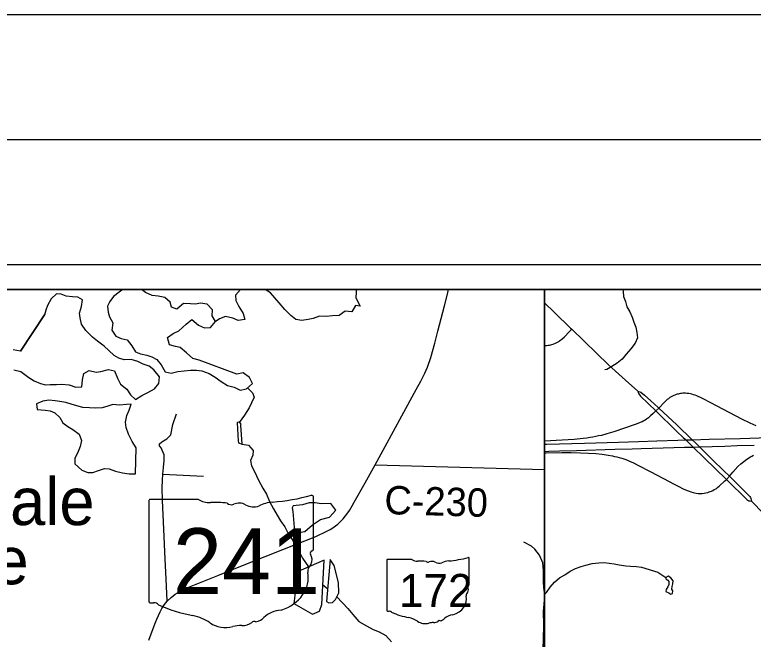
# Model space of a CAD drawing. Extents: x 25.6 to 80.6, y 0.2 to 24.5.
# Drawn here: x 38.894 to 41.848, y 19.73 to 22.23 of the extents above; entities that cross this region are included whole.
import ezdxf

# ---------------------------------------------------------------- set-up
doc = ezdxf.new("R2010")
doc.units = 0
for name, color, linetype in [('GM_X_County_Road', 7, 'Continuous'), ('GM_X_County_Road_Text', 7, 'Continuous'), ('GM_X_Interchange_Ramps', 7, 'Continuous'), ('GM_X_Interstate_Route', 7, 'Continuous'), ('GM_X_Minor_Lake', 7, 'Continuous'), ('GM_X_Minor_Lake_Text', 7, 'Continuous'), ('GM_X_Minor_River', 7, 'Continuous'), ('GM_X_State_Location', 7, 'Continuous'), ('GM_X_State_Route', 7, 'Continuous'), ('GM_X_State_Shield', 7, 'Continuous'), ('GM_X_Township_Road', 7, 'Continuous'), ('SH_Border', 7, 'Continuous'), ('SH_Cut_Line', 7, 'Continuous'), ('SH_Data', 7, 'Continuous'), ('SH_Text', 7, 'Continuous')]:
    doc.layers.add(name, color=color, linetype=linetype)

msp = doc.modelspace()

# ---------------------------------------------------------------- linework, layer by layer
at = {"layer": 'GM_X_County_Road'}
msp.add_line((40.3351, 20.429), (41.0128, 20.4098), dxfattribs=at)
at = {"layer": 'GM_X_Interchange_Ramps'}
for points in [[(41.8598, 20.5842), (41.8474, 20.5895), (41.8348, 20.5953), (41.8015, 20.612), (41.6785, 20.6768), (41.6477, 20.6929), (41.637, 20.698), (41.6272, 20.7027), (41.6218, 20.705), (41.6157, 20.7072), (41.6087, 20.7095), (41.6026, 20.7113), (41.5966, 20.7128), (41.5903, 20.7139), (41.5832, 20.7147), (41.5765, 20.7151), (41.571, 20.7151), (41.5664, 20.715), (41.5614, 20.7145), (41.557, 20.7139), (41.5518, 20.713), (41.5472, 20.712), (41.5431, 20.7109), (41.5389, 20.7096), (41.534, 20.708), (41.5296, 20.7061), (41.525, 20.7039), (41.52, 20.7011), (41.5142, 20.6977), (41.5083, 20.6934), (41.5035, 20.6895), (41.4979, 20.6846), (41.4925, 20.6794), (41.47, 20.656), (41.4587, 20.6442)], [(41.4587, 20.6442), (41.4473, 20.6337), (41.4372, 20.6245), (41.4288, 20.6171), (41.421, 20.611), (41.4158, 20.6076), (41.4104, 20.6045), (41.4031, 20.6007), (41.3959, 20.5975), (41.386, 20.5936), (41.375, 20.5896), (41.2902, 20.5612), (41.2617, 20.5525), (41.2401, 20.5467), (41.2291, 20.5441), (41.2183, 20.5417), (41.2067, 20.5395), (41.1951, 20.5375), (41.1825, 20.5357), (41.168, 20.5338), (41.1309, 20.5304), (41.0838, 20.5272), (41.0128, 20.5234)], [(41.0128, 20.4765), (41.0196, 20.4765), (41.0814, 20.4777), (41.1199, 20.4779), (41.1572, 20.4771), (41.1883, 20.4756), (41.218, 20.4734), (41.2428, 20.4709), (41.2674, 20.4676), (41.2845, 20.4644), (41.2933, 20.4626), (41.302, 20.4607), (41.312, 20.458), (41.3219, 20.455), (41.3335, 20.4511), (41.3441, 20.447), (41.3557, 20.4422), (41.3658, 20.4377), (41.3893, 20.4264), (41.4354, 20.4018), (41.4881, 20.3738), (41.5311, 20.3514), (41.5477, 20.3429), (41.5679, 20.3331), (41.5838, 20.3259), (41.591, 20.323), (41.5978, 20.3207), (41.6073, 20.3179), (41.6134, 20.3164), (41.6201, 20.3151), (41.6272, 20.3144), (41.6354, 20.3141), (41.6436, 20.3144), (41.651, 20.3152), (41.6586, 20.3166), (41.6662, 20.3185), (41.671, 20.3199), (41.6756, 20.3217), (41.6807, 20.3237), (41.6859, 20.3262), (41.6919, 20.3295), (41.6975, 20.333), (41.7016, 20.3357), (41.7066, 20.3394), (41.7116, 20.3435), (41.7345, 20.3647), (41.7406, 20.3703)], [(41.7406, 20.3703), (41.7524, 20.3838), (41.7662, 20.3997), (41.7864, 20.4214), (41.7982, 20.4324), (41.8097, 20.4419), (41.8227, 20.4514), (41.8364, 20.4601), (41.8425, 20.4636), (41.8494, 20.4673)]]:
    msp.add_lwpolyline(points, dxfattribs=at)
at = {"layer": 'GM_X_Interstate_Route'}
for points in [[(41.0128, 20.5109), (41.0222, 20.5112), (41.1725, 20.5159), (41.3093, 20.5196), (41.3888, 20.5224), (41.4619, 20.5246), (41.5466, 20.5275), (41.5778, 20.5283), (41.604, 20.529), (41.6721, 20.5308), (41.7951, 20.5346), (41.9095, 20.5377)], [(41.5733, 20.4988), (41.5875, 20.4992), (41.607, 20.4998), (41.6331, 20.5007), (41.7341, 20.5039), (41.7838, 20.5054), (41.8509, 20.5074)], [(41.0128, 20.4823), (41.0295, 20.4828), (41.073, 20.4843), (41.1413, 20.4864), (41.2942, 20.4911), (41.3638, 20.493), (41.3998, 20.4939), (41.488, 20.4963), (41.5733, 20.4988)]]:
    msp.add_lwpolyline(points, dxfattribs=at)
at = {"layer": 'GM_X_Minor_Lake'}
msp.add_line((41.5096, 19.9622), (41.5105, 19.95), dxfattribs=at)
for points in [[(39.3265, 21.1303), (39.3118, 21.1196), (39.2885, 21.1019), (39.2743, 21.0827), (39.2639, 21.0636), (39.2673, 21.0401), (39.2728, 21.0205), (39.286, 20.9971), (39.2825, 20.9682), (39.2973, 20.9433), (39.3186, 20.9337), (39.3429, 20.9286), (39.3614, 20.9053), (39.3769, 20.8812), (39.3967, 20.8731), (39.4225, 20.8673), (39.4416, 20.8607), (39.4614, 20.8503), (39.4791, 20.8285), (39.4954, 20.8006), (39.5189, 20.7955), (39.5462, 20.8027), (39.5712, 20.8045), (39.5962, 20.807), (39.6212, 20.8073), (39.6424, 20.8053), (39.6706, 20.7942), (39.6951, 20.7801), (39.7195, 20.7622), (39.7448, 20.7465), (39.7706, 20.74), (39.795, 20.7274), (39.8208, 20.733), (39.844, 20.7545), (39.8323, 20.7779), (39.8078, 20.7966), (39.7814, 20.791)], [(39.6313, 20.8477), (39.6062, 20.8542), (39.5809, 20.8767), (39.5556, 20.8985), (39.5366, 20.902), (39.5123, 20.9093), (39.5051, 20.9389), (39.5269, 20.9543), (39.5503, 20.9652), (39.5788, 20.9914), (39.602, 21.0106), (39.6281, 20.9874), (39.6532, 20.977), (39.676, 20.9788), (39.6969, 21.0026), (39.6838, 21.0252), (39.685, 21.0488), (39.6635, 21.0713), (39.6369, 21.0756), (39.6172, 21.0723), (39.596, 21.0736), (39.5686, 21.0748), (39.5416, 21.0524), (39.5203, 21.0598), (39.5155, 21.0802), (39.494, 21.099), (39.4667, 21.1032), (39.4431, 21.106), (39.4172, 21.1186), (39.4003, 21.1303)], [(38.8894, 20.8087), (38.9175, 20.8022), (38.9497, 20.7783), (38.9711, 20.7648), (38.997, 20.7538), (39.0167, 20.7494), (39.0357, 20.7504), (39.06, 20.7507), (39.0804, 20.7517), (39.1108, 20.749), (39.1374, 20.7394), (39.1624, 20.7413), (39.1651, 20.7686), (39.1701, 20.7945), (39.1912, 20.8061), (39.2186, 20.7989), (39.2383, 20.8021), (39.2685, 20.8101), (39.2921, 20.8043), (39.3046, 20.7756), (39.317, 20.7514), (39.3423, 20.732), (39.3562, 20.7086), (39.3769, 20.6906), (39.4025, 20.7061), (39.4259, 20.7185), (39.453, 20.7325), (39.4702, 20.7539), (39.4721, 20.7813), (39.4505, 20.8091), (39.4306, 20.8233), (39.407, 20.8314), (39.3857, 20.8426), (39.3598, 20.8499), (39.3317, 20.8495), (39.3104, 20.8554), (39.2906, 20.8658), (39.2699, 20.8868), (39.2507, 20.904), (39.2239, 20.9235), (39.2048, 20.9392), (39.1779, 20.967), (39.1602, 20.9918), (39.1546, 21.0168), (39.1528, 21.0358), (39.1601, 21.0624), (39.1643, 21.0891), (39.1452, 21.1002), (39.1247, 21.1015), (39.0989, 21.1042), (39.0798, 21.1116), (39.0601, 21.1137), (39.0391, 21.0929), (39.025, 21.0669), (39.0184, 21.0479), (39.0125, 21.0294)], [(38.8894, 20.8087), (38.9175, 20.8022), (38.9497, 20.7783), (38.9711, 20.7648), (38.997, 20.7538), (39.0167, 20.7494), (39.0357, 20.7504), (39.06, 20.7507), (39.0804, 20.7517), (39.1108, 20.749), (39.1374, 20.7394), (39.1624, 20.7413), (39.1651, 20.7686), (39.1701, 20.7945), (39.1912, 20.8061), (39.2186, 20.7989), (39.2383, 20.8021), (39.2685, 20.8101), (39.2921, 20.8043), (39.3046, 20.7756), (39.317, 20.7514), (39.3423, 20.732), (39.3562, 20.7086), (39.3769, 20.6906), (39.4025, 20.7061), (39.4259, 20.7185), (39.453, 20.7325), (39.4702, 20.7539), (39.4721, 20.7813), (39.4505, 20.8091), (39.4306, 20.8233), (39.407, 20.8314), (39.3857, 20.8426), (39.3598, 20.8499), (39.3317, 20.8495), (39.3104, 20.8554), (39.2906, 20.8658), (39.2699, 20.8868), (39.2507, 20.904), (39.2239, 20.9235), (39.2048, 20.9392), (39.1779, 20.967), (39.1602, 20.9918), (39.1546, 21.0168), (39.1528, 21.0358), (39.1601, 21.0624), (39.1643, 21.0891), (39.1452, 21.1002), (39.1247, 21.1015), (39.0989, 21.1042), (39.0798, 21.1116), (39.0601, 21.1137), (39.0391, 21.0929), (39.025, 21.0669), (39.0184, 21.0479), (39.0119, 21.0273)], [(39.0125, 21.0294), (38.9165, 20.8834)], [(38.9165, 20.8834), (39.0125, 21.0293)], [(38.9165, 20.8834), (38.8877, 20.8884)], [(38.9165, 20.8834), (38.8877, 20.8884)], [(39.7814, 20.791), (39.6313, 20.8477)], [(39.3792, 20.497), (39.363, 20.5226), (39.3483, 20.5513), (39.3396, 20.5778), (39.3371, 20.599), (39.342, 20.6264), (39.3516, 20.647), (39.3589, 20.6714), (39.34, 20.6704), (39.3127, 20.6671), (39.2854, 20.6698), (39.2658, 20.6635), (39.2431, 20.6571), (39.2158, 20.6561), (39.193, 20.6566), (39.1665, 20.6585), (39.1414, 20.6643), (39.1193, 20.6717), (39.098, 20.6775), (39.0744, 20.6818), (39.0547, 20.6853), (39.0304, 20.6881), (39.0054, 20.6832), (38.9805, 20.6731), (38.9838, 20.6503), (39.0157, 20.6477), (39.0347, 20.6448), (39.0545, 20.6367), (39.0737, 20.618), (39.0853, 20.5961), (39.1052, 20.5826), (39.1258, 20.57), (39.1511, 20.5513), (39.1605, 20.5263), (39.1547, 20.502), (39.1444, 20.4753), (39.1341, 20.4554), (39.1343, 20.4326), (39.1612, 20.4071), (39.1863, 20.3983), (39.2053, 20.3985), (39.2279, 20.4064), (39.2521, 20.4143), (39.2711, 20.413), (39.297, 20.4034), (39.3243, 20.3961), (39.3509, 20.3926), (39.3767, 20.3922)], [(39.803, 20.511), (39.7973, 20.5871), (39.7996, 20.5912), (39.7938, 20.5976), (39.7897, 20.5993), (39.7851, 20.5982), (39.7828, 20.5964), (39.7874, 20.525), (39.789, 20.5165)], [(39.789, 20.5165), (39.803, 20.511)], [(39.3767, 20.3922), (39.3792, 20.497)], [(40.011, 20.1778), (40.0141, 20.1672), (40.0218, 20.1605), (40.0309, 20.1576), (40.0536, 20.1616), (40.0844, 20.1878), (40.1168, 20.2102), (40.153, 20.219), (40.1777, 20.2473), (40.1584, 20.2745), (40.119, 20.2725), (40.0955, 20.276), (40.0712, 20.2765), (40.0448, 20.2686), (40.0069, 20.2651), (40.0032, 20.2559), (40.0057, 20.2415)], [(40.0057, 20.2415), (40.011, 20.1778)], [(40.0185, 19.9972), (40.0143, 19.906), (40.0094, 19.8741), (40.0842, 19.8309), (40.1129, 19.8426), (40.1224, 19.8701), (40.1309, 20.0471)], [(40.1309, 20.0471), (40.0185, 19.9972)], [(40.1405, 19.8817), (40.1504, 19.8765), (40.164, 19.8774), (40.1768, 19.8897), (40.1893, 19.9156), (40.1888, 19.9582), (40.1713, 20.0255), (40.1559, 20.0497)], [(40.1559, 20.0497), (40.1405, 19.8817)], [(41.5105, 19.95), (41.506, 19.9408), (41.4993, 19.9301), (41.4987, 19.9218), (41.5101, 19.9158), (41.5185, 19.9106), (41.5253, 19.9137), (41.5259, 19.9236), (41.5221, 19.9304), (41.5234, 19.9418), (41.5264, 19.9517), (41.527, 19.9646), (41.5185, 19.9767), (41.507, 19.9826), (41.498, 19.978), (41.4981, 19.9726), (41.5065, 19.9674), (41.5096, 19.9622)]]:
    msp.add_lwpolyline(points, dxfattribs=at)
at = {"layer": 'GM_X_Minor_River'}
for points in [[(39.7969, 21.1303), (39.7768, 21.1076), (39.7778, 21.0871), (39.7895, 21.0622), (39.8072, 21.0343), (39.8144, 21.0101), (39.7871, 21.0067), (39.7658, 21.0163), (39.7369, 21.0221), (39.712, 21.0127), (39.6958, 21.0014)], [(40.2589, 21.1303), (40.2597, 21.1193), (40.2585, 21.0965), (40.2755, 21.0633), (40.2565, 21.0661), (40.2417, 21.0408), (40.2159, 21.0443), (40.1918, 21.0266), (40.1645, 21.0255), (40.1388, 21.0222), (40.1122, 21.0242), (40.0873, 21.0147), (40.0669, 21.01), (40.0419, 21.0059), (40.0176, 21.0109), (39.9984, 21.0259), (39.9746, 21.0499), (39.9508, 21.0769), (39.9346, 21.0965), (39.9162, 21.1175), (39.8959, 21.1303)], [(41.3259, 21.1303), (41.3275, 21.123), (41.3285, 21.1025), (41.3363, 21.0828), (41.3419, 21.0609), (41.3543, 21.0405), (41.3629, 21.0193), (41.3707, 20.9997), (41.3777, 20.9793), (41.3825, 20.9588), (41.3843, 20.9376), (41.3755, 20.9154), (41.3576, 20.8924), (41.3389, 20.8717), (41.324, 20.851), (41.3037, 20.8355), (41.2819, 20.8216), (41.2623, 20.8107), (41.254, 20.8083)], [(39.8251, 20.737), (39.8345, 20.7276), (39.8449, 20.7172), (39.8519, 20.6992), (39.8403, 20.6771), (39.8315, 20.6562), (39.8124, 20.6278), (39.7915, 20.5986)], [(39.803, 20.511), (39.828, 20.5068), (39.8472, 20.4865), (39.846, 20.4675), (39.8364, 20.4454), (39.8412, 20.4249), (39.8521, 20.4015), (39.8692, 20.3668), (39.8855, 20.3358), (39.9009, 20.3109), (39.9127, 20.2815), (39.9282, 20.252), (39.9429, 20.2271), (39.9561, 20.2038), (39.9738, 20.1804), (39.9862, 20.1563), (40.0001, 20.1337), (40.0195, 20.105), (40.0311, 20.0816), (40.0443, 20.0552), (40.0692, 20.0197)], [(41.0128, 19.9092), (41.0208, 19.9181), (41.0349, 19.9395), (41.0521, 19.9595), (41.0731, 19.9757), (41.0942, 19.9881), (41.1159, 20.0036), (41.137, 20.0137), (41.1589, 20.0216), (41.1785, 20.0271), (41.2034, 20.0343), (41.2299, 20.0361), (41.2519, 20.0372), (41.2716, 20.0352), (41.2913, 20.0324), (41.3118, 20.0288), (41.3376, 20.0246), (41.3573, 20.0225), (41.3808, 20.0221), (41.4013, 20.0193), (41.4661, 19.9994), (41.498, 19.978)], [(40.1451, 19.9329), (40.1261, 19.9475)], [(40.182, 19.9005), (40.2257, 19.8538), (40.2465, 19.8297), (40.2703, 19.8012), (40.3001, 19.7848), (40.3276, 19.7692), (40.3512, 19.7596), (40.3779, 19.7455), (40.401, 19.7207)]]:
    msp.add_lwpolyline(points, dxfattribs=at)
at = {"layer": 'GM_X_State_Route'}
msp.add_line((41.568, 20.5379), (41.575, 20.531), dxfattribs=at)
for points in [[(39.4294, 19.7265), (39.4558, 19.7951), (39.462, 19.8113), (39.4682, 19.8261), (39.4748, 19.8397), (39.4824, 19.8538), (39.4924, 19.8691), (39.5031, 19.8823), (39.5186, 19.8979), (39.5355, 19.9104), (39.5542, 19.9214), (39.5715, 19.9303), (39.5928, 19.9398), (39.7059, 19.9861), (39.8248, 20.0331), (39.9666, 20.0896), (40.0973, 20.1423), (40.142, 20.1625), (40.1554, 20.1698), (40.1659, 20.1765), (40.1766, 20.1839), (40.1857, 20.1912), (40.1957, 20.2005), (40.2072, 20.2125), (40.217, 20.2244), (40.2256, 20.236), (40.2324, 20.2461), (40.2437, 20.2645), (40.2519, 20.2789), (40.2954, 20.357), (40.3351, 20.429), (40.3752, 20.5024), (40.4422, 20.6253), (40.4993, 20.7297), (40.5179, 20.7642), (40.5341, 20.7952), (40.5448, 20.82), (40.558, 20.8584), (40.574, 20.9151), (40.5865, 20.9639), (40.6125, 21.0646), (40.6231, 21.1067), (40.6283, 21.1303)], [(41.0128, 21.0776), (41.0527, 21.0388), (41.1167, 20.9763), (41.1214, 20.9717), (41.1696, 20.9253), (41.222, 20.874), (41.268, 20.8303), (41.2973, 20.8034), (41.3371, 20.7677), (41.386, 20.7229)], [(41.386, 20.7229), (41.3871, 20.7182), (41.3895, 20.7134), (41.3974, 20.7037), (41.4587, 20.6442), (41.5427, 20.5626), (41.568, 20.5379)], [(41.386, 20.7229), (41.3891, 20.7227), (41.3945, 20.721), (41.3977, 20.7192), (41.4127, 20.7079), (41.4381, 20.685), (41.4679, 20.658), (41.47, 20.656), (41.5422, 20.5881), (41.604, 20.529), (41.6186, 20.515), (41.6331, 20.5007), (41.684, 20.4503), (41.7303, 20.4051), (41.7524, 20.3838)], [(41.575, 20.531), (41.5778, 20.5283), (41.607, 20.4998), (41.6511, 20.4567), (41.7406, 20.3703)], [(41.7524, 20.3838), (41.7545, 20.3818), (41.7862, 20.3503), (41.8098, 20.3264), (41.8338, 20.3013), (41.8363, 20.2972), (41.8383, 20.2937), (41.84, 20.2883), (41.8408, 20.2836)], [(41.7406, 20.3703), (41.7557, 20.3556), (41.8106, 20.3016), (41.8224, 20.2896), (41.8258, 20.2868), (41.8299, 20.2849), (41.8353, 20.284), (41.8408, 20.2836)], [(41.8408, 20.2836), (41.8564, 20.2671), (41.8734, 20.2492), (41.8956, 20.2258), (41.9209, 20.2004), (41.9694, 20.1517)]]:
    msp.add_lwpolyline(points, dxfattribs=at)
at = {"layer": 'GM_X_State_Shield'}
for p, q in [((40.0884, 20.0906), (40.0884, 20.3)), ((39.4293, 20.2832), (39.4293, 19.8829)), ((39.6288, 20.2901), (39.4358, 20.2901)), ((40.0884, 20.0907), (40.0884, 20.0906)), ((40.3817, 20.046), (40.3817, 19.8458)), ((40.4814, 20.0494), (40.3849, 20.0494)), ((40.7112, 19.9497), (40.7112, 20.0544)), ((40.7112, 19.9497), (40.7112, 19.9497))]:
    msp.add_line(p, q, dxfattribs=at)
for centre, major_axis, start_param, end_param in [((39.8536, 20.8357), (0.699, 0), 4.814394, 5.042369), ((40.0811, 20.3008), (0.00734, 0), 6.141152, 7.989035), ((39.4368, 20.284), (0.00764, 0), 1.712693, 3.28349), ((39.6748, 20.3365), (0.0741, 0), 4.042523, 4.731795), ((39.6993, 20.0654), (0.2659, 0), 1.404758, 1.657858), ((39.7597, 20.2861), (0.0214, 0), 3.836095, 5.185415), ((39.7911, 20.2398), (0.0444, 0), 0.950623, 2.079405), ((39.8484, 20.3033), (0.0534, 0), 4.081561, 5.145723), ((39.9428, 20.1678), (0.1406, 0), 1.699011, 2.107814), ((40.0806, 20.0898), (0.00785, 0), 5.05454, 6.418171), ((40.0867, 20.0752), (0.0114, 0), 1.883978, 3.671073), ((40.0145, 20.0488), (0.0682, 0), 5.934695, 6.695948), ((40.1147, 20.003), (0.0496, 0), 2.387724, 3.262537), ((40.3854, 20.0464), (0.00382, 0), 1.712693, 3.28349), ((40.5044, 20.0726), (0.037, 0), 4.042523, 4.731795), ((40.5167, 19.9371), (0.133, 0), 1.404758, 1.657858), ((40.5469, 20.0474), (0.0107, 0), 3.836095, 5.185415), ((40.5626, 20.0243), (0.0222, 0), 0.950623, 2.079405), ((40.5912, 20.056), (0.0267, 0), 4.081561, 5.145723), ((40.6384, 19.9883), (0.0703, 0), 1.699011, 2.107814), ((40.5938, 20.3222), (0.3495, 0), 4.814394, 5.042369), ((40.7076, 20.0548), (0.00367, 0), 6.141152, 7.989035), ((39.8928, 19.9763), (0.1748, 0), 5.101752, 6.440018), ((40.7104, 19.942), (0.00568, 0), 1.883978, 3.671073), ((40.7073, 19.9493), (0.00393, 0), 5.05454, 6.418171), ((40.7244, 19.9059), (0.0248, 0), 2.387724, 3.262537), ((40.6743, 19.9288), (0.0341, 0), 5.934695, 6.695948), ((39.4369, 19.882), (0.0077, 0), 3.00124, 4.508301), ((40.6134, 19.8926), (0.0874, 0), 5.101752, 6.440018), ((39.438, 19.923), (0.0588, 0), 4.665946, 4.897461), ((39.4501, 19.8598), (0.0212, 0), 0.519207, 1.627899), ((39.7177, 20.2194), (0.5048, 0), 4.195997, 4.488961), ((39.5672, 19.7031), (0.1579, 0), 0.823519, 1.323587), ((39.9665, 19.7706), (0.0958, 0), 1.647645, 2.488434), ((40.3855, 19.8454), (0.00385, 0), 3.00124, 4.508301), ((40.3861, 19.8659), (0.0294, 0), 4.665946, 4.897461), ((40.3921, 19.8343), (0.0106, 0), 0.519207, 1.627899), ((40.5259, 20.0141), (0.2524, 0), 4.195997, 4.488961), ((40.6503, 19.7897), (0.0479, 0), 1.647645, 2.488434), ((39.7381, 19.8578), (0.1002, 0), 4.026481, 4.996735), ((39.8033, 19.8279), (0.0534, 0), 4.691044, 5.507374), ((39.8516, 19.7891), (0.015, 0), 1.147584, 2.315152), ((39.8452, 19.8441), (0.0565, 0), 4.937069, 5.64225), ((40.4506, 19.7559), (0.079, 0), 0.823519, 1.323587), ((40.5361, 19.8333), (0.0501, 0), 4.026481, 4.996735), ((40.565, 19.7641), (0.0412, 0), 1.495662, 1.94098), ((40.5687, 19.8183), (0.0267, 0), 4.691044, 5.507374), ((40.5928, 19.7989), (0.00752, 0), 1.147584, 2.315152), ((40.5896, 19.8265), (0.0282, 0), 4.937069, 5.64225), ((39.796, 19.7195), (0.0824, 0), 1.495662, 1.94098)]:
    msp.add_ellipse(centre, major_axis=major_axis, ratio=0.8, start_param=start_param, end_param=end_param, dxfattribs=at)
at = {"layer": 'GM_X_Township_Road'}
for p, q in [((39.4859, 20.3906), (39.6488, 20.3832)), ((41.0128, 19.9163), (41.0107, 19.9375))]:
    msp.add_line(p, q, dxfattribs=at)
for points in [[(41.0128, 20.9067), (41.0214, 20.9069), (41.0272, 20.9074), (41.0325, 20.9082), (41.0377, 20.9091), (41.0422, 20.9102), (41.047, 20.9115), (41.0505, 20.9129), (41.0573, 20.9158), (41.065, 20.9198), (41.0696, 20.9226), (41.0733, 20.9253), (41.0776, 20.9287), (41.0821, 20.9322), (41.0921, 20.9415), (41.111, 20.961), (41.1214, 20.9717)], [(39.5031, 19.8823), (39.4986, 19.9729), (39.4946, 20.0508), (39.4899, 20.1714), (39.4841, 20.2852), (39.4834, 20.3361), (39.4845, 20.3666), (39.4859, 20.3906), (39.4883, 20.4181), (39.4914, 20.4457), (39.491, 20.4686), (39.4794, 20.4968), (39.4728, 20.5045), (39.4724, 20.5123), (39.482, 20.5206), (39.5018, 20.5331), (39.5173, 20.5482), (39.5264, 20.5905), (39.5405, 20.6331)], [(41.0128, 19.9374), (41.0107, 19.9375), (41.0085, 19.9595), (41.0093, 20.0056), (41.0058, 20.0369), (40.993, 20.0667), (40.9745, 20.0916), (40.9603, 20.103), (40.9305, 20.1193)], [(40.7082, 19.5587), (40.7342, 19.5583), (40.7726, 19.5582), (40.8152, 19.5625), (40.8493, 19.5682), (40.899, 19.5724), (40.9445, 19.5852), (40.9757, 19.5994), (40.9942, 19.615), (41.0056, 19.6604), (41.0085, 19.7286), (41.0099, 19.7897), (41.0085, 19.8409), (41.0128, 19.8866)]]:
    msp.add_lwpolyline(points, dxfattribs=at)
at = {"layer": 'SH_Border'}
msp.add_lwpolyline([(37.0128, 21.7303), (69.0128, 21.7303), (69.0128, 0.7303), (37.0128, 0.7303)], close=True, dxfattribs=at)
at = {"layer": 'SH_Cut_Line'}
msp.add_lwpolyline([(35.5128, 0.2303), (69.5128, 0.2303), (69.5128, 22.2303), (35.5128, 22.2303)], close=True, dxfattribs=at)
at = {"layer": 'SH_Data'}
for p, q in [((37.5128, 21.2303), (44.5128, 21.2303)), ((37.6128, 21.1303), (44.4128, 21.1303)), ((37.6128, 21.1303), (44.4128, 21.1303)), ((41.0128, 21.1303), (41.0128, 14.3303))]:
    msp.add_line(p, q, dxfattribs=at)
at = {"layer": 'SH_Text'}
for points in [[(37.6128, 21.1303), (44.4128, 21.1303), (44.4128, 14.3303), (37.6128, 14.3303)], [(37.6128, 21.1303), (44.4128, 21.1303), (44.4128, 14.3303), (37.6128, 14.3303)], [(37.6128, 17.7303), (41.0128, 17.7303), (41.0128, 21.1303), (37.6128, 21.1303)], [(37.6128, 17.7303), (41.0128, 17.7303), (41.0128, 21.1303), (37.6128, 21.1303)], [(41.0128, 17.7303), (44.4128, 17.7303), (44.4128, 21.1303), (41.0128, 21.1303)], [(41.0128, 17.7303), (44.4128, 17.7303), (44.4128, 21.1303), (41.0128, 21.1303)]]:
    msp.add_lwpolyline(points, close=True, dxfattribs=at)

# ---------------------------------------------------------------- texts
at = {"layer": 'GM_X_County_Road_Text'}
msp.add_text('C-230', height=0.11364, rotation=358.3486, dxfattribs=at).set_placement((40.371, 20.2316))
at = {"layer": 'GM_X_Minor_Lake_Text'}
for s, rotation, p in [('Willowdale', 359.9766, (38.0021, 20.1878)), ('Lake', 359.9767, (38.3999, 19.9507))]:
    msp.add_text(s, height=0.18945, rotation=rotation, dxfattribs=at).set_placement(p)
at = {"layer": 'GM_X_State_Location'}
for s in ['s', 'r']:
    msp.add_text(s, height=0.000379, dxfattribs=at).set_placement((39.7971, 19.9788))
msp.add_text('241', height=0.000379, rotation=0, dxfattribs=at).set_placement((39.6634, 19.9512))
at = {"layer": 'GM_X_State_Shield'}
for s, height, p in [('241', 0.26367, (39.5264, 19.9111)), ('172', 0.13184, (40.4307, 19.86))]:
    msp.add_text(s, height=height, dxfattribs=at).set_placement(p)

doc.saveas('drawing.dxf')
